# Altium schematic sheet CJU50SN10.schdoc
size 127 x 101 mm
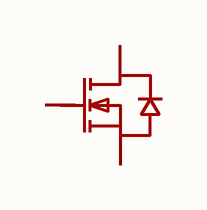
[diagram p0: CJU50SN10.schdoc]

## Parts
Q?  cju50sn10  [TO-252-2_L6.6-W6.1-P4.57-LS10.0-BR-1]  (value not drawn)

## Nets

Not connected (* = marked no-connect by the designer): Q? 1(G) 2(D) 3(S)

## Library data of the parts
Q? = cju50sn10: 数量:1个N沟道;漏源电压(Vdss):100V;连续漏极电流(Id):50A;导通电阻(RDS(on)):16.5mΩ@10V;耗散功率(Pd):50W;阈值电压(Vgs(th)):-;; Manufacturer: CJ(江苏长电/长晶); AddInBom: yes; ModelId: 4113ec4a058842b08e2585e7304bd9b4; ModelTransform: 401.574,259.842,0,0,0,0,-36.417,0,0; Number: 1个N沟道; Drain to Source Voltage: 100V; Current - Continuous Drain(Id): 50A; Pd - Power Dissipation: 50W; Gate Charge(Qg): 15.7nC@10V; Input Capacitance(Ciss): 975.3pF; Reverse Transfer Capacitance (Crss@Vds): 9.4pF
